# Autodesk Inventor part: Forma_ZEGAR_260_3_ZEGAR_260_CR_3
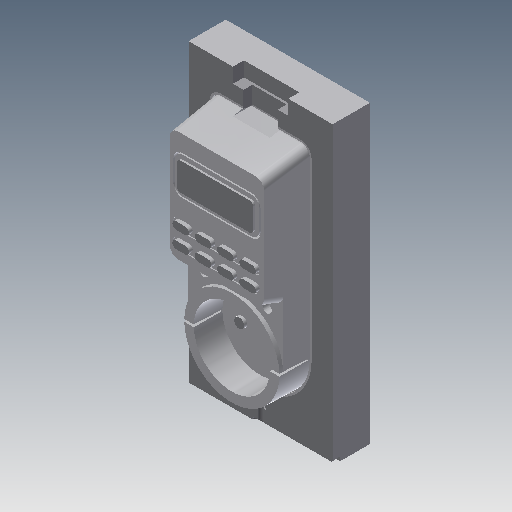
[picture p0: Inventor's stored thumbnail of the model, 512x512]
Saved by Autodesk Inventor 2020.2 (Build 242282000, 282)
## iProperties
Created: 2015-01
Part Number: Forma_ZEGAR_260_3_ZEGAR_260_CR_3
Material: Ogólny
Document SubType Name: Modeling
Designer: F.Stasiak
Density: 1 g/cm^3
Appearance: Domyślna
Catalog Web Link: www.expertbooks.pl
Manager: www.cadconsulting.pl
Company: Fabian Stasiak CAD Consulting
Author: F.Stasiak
Subject: Zbiór ćwiczeń. Autodesk Inventor 2020. Kurs Professional
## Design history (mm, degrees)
node "Forma_ZEGAR_260_3_ZEGAR_260_CR_Base"
feature "Rzeźbienie3"
feature "Bryła1::Forma_ZEGAR_260_3_ZEGAR_260_CR_Base"
tag "Bryła wyprowadzona1"
node "Bryła1"
feature "Forma_ZEGAR_260_3_ZEGAR_260_CR_Base_Bodies"
feature "Powierzchnia3"
body "Srf3"
